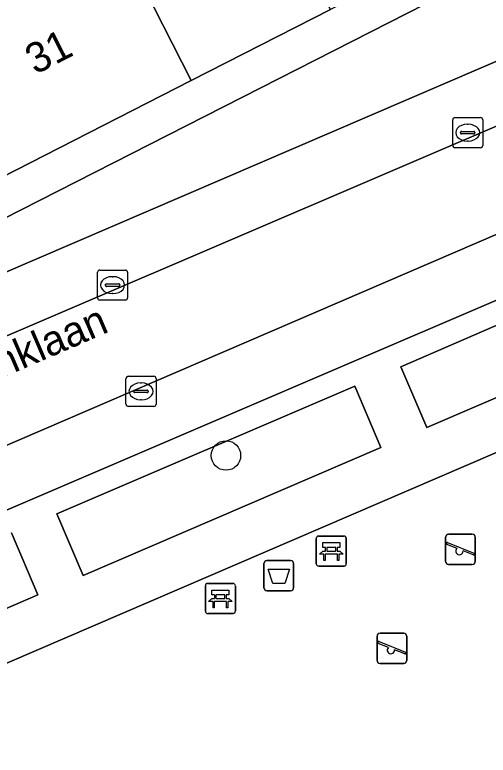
# Model space of a CAD drawing. Extents: x 162344 to 162869, y 381217 to 381818.
# Drawn here: x 162510.38 to 162526.14, y 381519.73 to 381544.36 of the extents above; entities that cross this region are included whole.
import ezdxf

# ---------------------------------------------------------------- set-up
doc = ezdxf.new("R2010")
doc.units = 0
for name, color, linetype in [('IMGEO_Afvalbak', 7, 'Continuous'), ('IMGEO_Bank', 7, 'Continuous'), ('IMGEO_Boom', 7, 'Continuous'), ('IMGEO_Erf', 7, 'Continuous'), ('IMGEO_Groenvoorziening', 7, 'Continuous'), ('IMGEO_Kolk', 7, 'Continuous'), ('IMGEO_Openbare_ruimte_label', 7, 'Continuous'), ('IMGEO_Pand', 7, 'Continuous'), ('IMGEO_Pand_nummerreeks', 7, 'Continuous'), ('IMGEO_Parkeervlak_open', 7, 'Continuous'), ('IMGEO_Rijbaan_lokaal_open', 7, 'Continuous'), ('IMGEO_Speelvoorziening', 7, 'Continuous'), ('IMGEO_Terreindeel_zand', 7, 'Continuous'), ('IMGEO_Voetpad_open', 7, 'Continuous')]:
    doc.layers.add(name, color=color, linetype=linetype)

msp = doc.modelspace()

# ---------------------------------------------------------------- linework, layer by layer
at = {"layer": 'IMGEO_Afvalbak'}
for p, q in [((162518.676, 381525.301), (162518.676, 381526.101)), ((162518.676, 381526.101), (162518.676, 381525.301)), ((162518.776, 381526.201), (162519.566, 381526.201)), ((162519.566, 381526.201), (162518.776, 381526.201)), ((162519.666, 381526.101), (162519.666, 381525.301)), ((162519.666, 381525.301), (162519.666, 381526.101)), ((162519.566, 381525.201), (162518.776, 381525.201)), ((162518.776, 381525.201), (162519.566, 381525.201))]:
    msp.add_line(p, q, dxfattribs=at)
msp.add_lwpolyline([(162518.819, 381525.915), (162519.523, 381525.915), (162519.374, 381525.445), (162518.968, 381525.445), (162518.819, 381525.915)], dxfattribs=at)
for centre, start, end in [((162518.776, 381526.101), 90, 180), ((162518.776, 381526.101), 90, 180), ((162519.566, 381526.101), 0, 90), ((162519.566, 381526.101), 360, 90), ((162518.776, 381525.301), 180, 270), ((162518.776, 381525.301), 180, 270), ((162519.566, 381525.301), 270, 0), ((162519.566, 381525.301), 270, 0)]:
    msp.add_arc(centre, 0.1, start, end, dxfattribs=at)
at = {"layer": 'IMGEO_Bank'}
for p, q in [((162520.42, 381526.095), (162520.42, 381526.936)), ((162520.42, 381526.936), (162520.42, 381526.095)), ((162520.495, 381527.02), (162521.336, 381527.02)), ((162521.336, 381527.02), (162520.495, 381527.02)), ((162521.42, 381526.945), (162521.42, 381526.104)), ((162521.42, 381526.104), (162521.42, 381526.945)), ((162520.729, 381526.526), (162520.729, 381526.632)), ((162520.773, 381526.632), (162520.773, 381526.526)), ((162521.061, 381526.638), (162520.779, 381526.638)), ((162521.067, 381526.526), (162521.067, 381526.632)), ((162521.111, 381526.632), (162521.111, 381526.526)), ((162521.117, 381526.418), (162520.724, 381526.418)), ((162520.779, 381526.52), (162521.061, 381526.52)), ((162521.345, 381526.02), (162520.504, 381526.02)), ((162520.504, 381526.02), (162521.345, 381526.02)), ((162516.728, 381524.518), (162516.728, 381525.359)), ((162516.728, 381525.359), (162516.728, 381524.518)), ((162516.803, 381525.443), (162517.644, 381525.443)), ((162517.644, 381525.443), (162516.803, 381525.443)), ((162517.728, 381525.368), (162517.728, 381524.527)), ((162517.728, 381524.527), (162517.728, 381525.368)), ((162517.037, 381524.949), (162517.037, 381525.055)), ((162517.081, 381525.055), (162517.081, 381524.949)), ((162517.369, 381525.061), (162517.087, 381525.061)), ((162517.375, 381524.949), (162517.375, 381525.055)), ((162517.419, 381525.055), (162517.419, 381524.949)), ((162517.425, 381524.841), (162517.032, 381524.841)), ((162517.087, 381524.943), (162517.369, 381524.943)), ((162517.653, 381524.443), (162516.812, 381524.443)), ((162516.812, 381524.443), (162517.653, 381524.443))]:
    msp.add_line(p, q, dxfattribs=at)
for points in [[(162520.723, 381526.638), (162520.637, 381526.638), (162520.637, 381526.799), (162521.2, 381526.799), (162521.2, 381526.638), (162521.117, 381526.638)], [(162520.667, 381526.418), (162520.525, 381526.418), (162520.637, 381526.52), (162520.723, 381526.52)], [(162520.717, 381526.411), (162520.717, 381526.204), (162520.674, 381526.204), (162520.674, 381526.411)], [(162521.117, 381526.52), (162521.2, 381526.52), (162521.312, 381526.418), (162521.173, 381526.418)], [(162521.167, 381526.411), (162521.167, 381526.204), (162521.123, 381526.204), (162521.123, 381526.411)], [(162517.031, 381525.061), (162516.945, 381525.061), (162516.945, 381525.222), (162517.508, 381525.222), (162517.508, 381525.061), (162517.425, 381525.061)], [(162516.975, 381524.841), (162516.833, 381524.841), (162516.945, 381524.943), (162517.031, 381524.943)], [(162517.025, 381524.834), (162517.025, 381524.627), (162516.982, 381524.627), (162516.982, 381524.834)], [(162517.425, 381524.943), (162517.508, 381524.943), (162517.62, 381524.841), (162517.481, 381524.841)], [(162517.475, 381524.834), (162517.475, 381524.627), (162517.431, 381524.627), (162517.431, 381524.834)]]:
    msp.add_lwpolyline(points, dxfattribs=at)
for centre, radius, start, end in [((162520.498, 381526.942), 0.0779, 92.4484, 184.2845), ((162520.498, 381526.942), 0.0779, 92.4484, 184.2845), ((162521.342, 381526.942), 0.0779, 2.4484, 94.2845), ((162521.342, 381526.942), 0.0779, 2.4484, 94.2845), ((162520.722, 381526.631), 0.00671, 2.8957, 87.1043), ((162520.779, 381526.631), 0.00671, 92.8957, 177.1043), ((162521.061, 381526.631), 0.00671, 2.8957, 87.1043), ((162521.118, 381526.631), 0.00671, 92.8957, 177.1043), ((162520.667, 381526.411), 0.00671, 2.8957, 87.1043), ((162520.724, 381526.411), 0.00671, 92.8957, 177.1043), ((162520.722, 381526.527), 0.00671, 272.8957, 357.1043), ((162520.779, 381526.527), 0.00671, 182.8957, 267.1043), ((162521.061, 381526.527), 0.00671, 272.8957, 357.1043), ((162521.118, 381526.527), 0.00671, 182.8957, 267.1043), ((162521.116, 381526.411), 0.00671, 2.8957, 87.1043), ((162521.173, 381526.411), 0.00671, 92.8957, 177.1043), ((162520.498, 381526.098), 0.0779, 182.4484, 274.2845), ((162520.498, 381526.098), 0.0779, 182.4484, 274.2845), ((162521.342, 381526.098), 0.0779, 272.4484, 4.2845), ((162521.342, 381526.098), 0.0779, 272.4484, 4.2845), ((162516.806, 381525.365), 0.0779, 92.4484, 184.2845), ((162516.806, 381525.365), 0.0779, 92.4484, 184.2845), ((162517.65, 381525.365), 0.0779, 2.4484, 94.2845), ((162517.65, 381525.365), 0.0779, 2.4484, 94.2845), ((162517.03, 381525.054), 0.00671, 2.8957, 87.1043), ((162517.087, 381525.054), 0.00671, 92.8957, 177.1043), ((162517.369, 381525.054), 0.00671, 2.8957, 87.1043), ((162517.426, 381525.054), 0.00671, 92.8957, 177.1043), ((162516.975, 381524.834), 0.00671, 2.8957, 87.1043), ((162517.032, 381524.834), 0.00671, 92.8957, 177.1043), ((162517.03, 381524.95), 0.00671, 272.8957, 357.1043), ((162517.087, 381524.95), 0.00671, 182.8957, 267.1043), ((162517.369, 381524.95), 0.00671, 272.8957, 357.1043), ((162517.426, 381524.95), 0.00671, 182.8957, 267.1043), ((162517.424, 381524.834), 0.00671, 2.8957, 87.1043), ((162517.481, 381524.834), 0.00671, 92.8957, 177.1043), ((162516.806, 381524.521), 0.0779, 182.4484, 274.2845), ((162516.806, 381524.521), 0.0779, 182.4484, 274.2845), ((162517.65, 381524.521), 0.0779, 272.4484, 4.2845), ((162517.65, 381524.521), 0.0779, 272.4484, 4.2845)]:
    msp.add_arc(centre, radius, start, end, dxfattribs=at)
at = {"layer": 'IMGEO_Boom'}
msp.add_circle((162517.413, 381529.699), 0.489, dxfattribs=at)
at = {"layer": 'IMGEO_Erf'}
msp.add_lwpolyline([(162532.638, 381549.091), (162532.073, 381550.22), (162525.378, 381546.813), (162520.892, 381544.53), (162516.259, 381542.172), (162509.427, 381538.695), (162509.986, 381537.559)], close=True, dxfattribs=at)
at = {"layer": 'IMGEO_Groenvoorziening'}
for points in [[(162538.381, 381539.216), (162523.23, 381532.652), (162524.096, 381530.629), (162537.402, 381536.341)], [(162499.674, 381520.107), (162511.154, 381525.065), (162510.27, 381527.123)]]:
    msp.add_lwpolyline(points, dxfattribs=at)
msp.add_lwpolyline([(162521.7, 381532.007), (162511.787, 381527.762), (162512.662, 381525.701), (162522.572, 381529.968)], close=True, dxfattribs=at)
at = {"layer": 'IMGEO_Kolk'}
for p, q in [((162524.96, 381540.012), (162524.96, 381540.864)), ((162525.035, 381540.938), (162525.887, 381540.938)), ((162525.961, 381540.864), (162525.961, 381540.012)), ((162525.448, 381540.718), (162525.473, 381540.718)), ((162525.219, 381540.432), (162525.219, 381540.444)), ((162525.657, 381540.395), (162525.259, 381540.395)), ((162525.262, 381540.481), (162525.66, 381540.481)), ((162525.703, 381540.444), (162525.703, 381540.432)), ((162525.471, 381540.158), (162525.446, 381540.158)), ((162525.887, 381539.938), (162525.035, 381539.938)), ((162513.138, 381534.941), (162513.138, 381535.793)), ((162513.213, 381535.867), (162514.065, 381535.867)), ((162513.626, 381535.647), (162513.651, 381535.647)), ((162514.139, 381535.793), (162514.139, 381534.941)), ((162513.44, 381535.41), (162513.838, 381535.41)), ((162513.397, 381535.361), (162513.397, 381535.373)), ((162513.835, 381535.324), (162513.437, 381535.324)), ((162513.881, 381535.373), (162513.881, 381535.361)), ((162513.649, 381535.087), (162513.624, 381535.087)), ((162514.065, 381534.867), (162513.213, 381534.867)), ((162514.085, 381531.406), (162514.085, 381532.258)), ((162514.16, 381532.332), (162515.012, 381532.332)), ((162515.086, 381532.258), (162515.086, 381531.406)), ((162514.573, 381532.112), (162514.598, 381532.112)), ((162514.344, 381531.826), (162514.344, 381531.838)), ((162514.782, 381531.789), (162514.384, 381531.789)), ((162514.387, 381531.875), (162514.785, 381531.875)), ((162514.828, 381531.838), (162514.828, 381531.826)), ((162514.596, 381531.552), (162514.571, 381531.552)), ((162515.012, 381531.332), (162514.16, 381531.332))]:
    msp.add_line(p, q, dxfattribs=at)
for points in [[(162524.96, 381540.012), (162524.96, 381540.864)], [(162525.035, 381540.938), (162525.887, 381540.938)], [(162525.961, 381540.864), (162525.961, 381540.012)], [(162525.887, 381539.938), (162525.035, 381539.938)], [(162513.138, 381534.941), (162513.138, 381535.793)], [(162513.213, 381535.867), (162514.065, 381535.867)], [(162514.139, 381535.793), (162514.139, 381534.941)], [(162514.065, 381534.867), (162513.213, 381534.867)], [(162514.085, 381531.406), (162514.085, 381532.258)], [(162514.16, 381532.332), (162515.012, 381532.332)], [(162515.086, 381532.258), (162515.086, 381531.406)], [(162515.012, 381531.332), (162514.16, 381531.332)]]:
    msp.add_lwpolyline(points, dxfattribs=at)
for centre, radius, start, end in [((162525.037, 381540.862), 0.0765, 91.552, 178.448), ((162525.037, 381540.862), 0.0765, 91.552, 178.448), ((162525.885, 381540.862), 0.0765, 1.552, 88.448), ((162525.885, 381540.862), 0.0765, 1.552, 88.448), ((162525.259, 381540.441), 0.0403, 85.8775, 175.7526), ((162525.256, 381540.431), 0.0366, 178.938, 274.7102), ((162525.66, 381540.438), 0.043, 264.8664, 352.4533), ((162525.664, 381540.443), 0.0386, 1.7309, 96.639), ((162525.037, 381540.014), 0.0765, 181.552, 268.448), ((162525.037, 381540.014), 0.0765, 181.552, 268.448), ((162525.885, 381540.014), 0.0765, 271.552, 358.448), ((162525.885, 381540.014), 0.0765, 271.552, 358.448), ((162513.215, 381535.791), 0.0765, 91.552, 178.448), ((162513.215, 381535.791), 0.0765, 91.552, 178.448), ((162514.063, 381535.791), 0.0765, 1.552, 88.448), ((162514.063, 381535.791), 0.0765, 1.552, 88.448), ((162513.437, 381535.37), 0.0403, 85.8775, 175.7526), ((162513.842, 381535.372), 0.0386, 1.7309, 96.639), ((162513.434, 381535.36), 0.0366, 178.938, 274.7102), ((162513.838, 381535.367), 0.043, 264.8664, 352.4533), ((162513.215, 381534.943), 0.0765, 181.552, 268.448), ((162513.215, 381534.943), 0.0765, 181.552, 268.448), ((162514.063, 381534.943), 0.0765, 271.552, 358.448), ((162514.063, 381534.943), 0.0765, 271.552, 358.448), ((162514.162, 381532.256), 0.0765, 91.552, 178.448), ((162514.162, 381532.256), 0.0765, 91.552, 178.448), ((162515.01, 381532.256), 0.0765, 1.552, 88.448), ((162515.01, 381532.256), 0.0765, 1.552, 88.448), ((162514.384, 381531.835), 0.0403, 85.8775, 175.7526), ((162514.381, 381531.825), 0.0366, 178.938, 274.7102), ((162514.785, 381531.832), 0.043, 264.8664, 352.4533), ((162514.789, 381531.837), 0.0386, 1.7309, 96.639), ((162514.162, 381531.408), 0.0765, 181.552, 268.448), ((162514.162, 381531.408), 0.0765, 181.552, 268.448), ((162515.01, 381531.408), 0.0765, 271.552, 358.448), ((162515.01, 381531.408), 0.0765, 271.552, 358.448)]:
    msp.add_arc(centre, radius, start, end, dxfattribs=at)
for centre, major_axis, ratio, start_param, end_param in [((162525.447, 381540.438), (-0.387, 0.002), 0.722429, 4.712389, 7.853982), ((162525.472, 381540.438), (-0.39, 0.002), 0.717154, 1.570796, 4.712389), ((162513.625, 381535.367), (-0.387, 0.002), 0.722429, 4.712389, 7.853982), ((162513.65, 381535.367), (-0.39, 0.002), 0.717154, 1.570796, 4.712389), ((162514.572, 381531.832), (-0.387, 0.002), 0.722429, 4.712389, 7.853982), ((162514.597, 381531.832), (-0.39, 0.002), 0.717154, 1.570796, 4.712389)]:
    msp.add_ellipse(centre, major_axis=major_axis, ratio=ratio, start_param=start_param, end_param=end_param, dxfattribs=at)
at = {"layer": 'IMGEO_Pand'}
for points in [[(162516.259, 381542.172), (162520.892, 381544.53), (162517.175, 381551.836), (162510.497, 381548.437), (162512.355, 381544.785), (162514.399, 381545.825)], [(162514.399, 381545.825), (162512.355, 381544.785), (162510.497, 381548.437), (162506.006, 381546.152), (162505.709, 381546.001), (162507.159, 381543.152), (162509.427, 381538.695), (162516.259, 381542.172)]]:
    msp.add_lwpolyline(points, close=True, dxfattribs=at)
at = {"layer": 'IMGEO_Parkeervlak_open'}
for points in [[(162529.63, 381544.187), (162503.672, 381533.049)], [(162501.836, 381530.146), (162533.181, 381543.553)], [(162534.166, 381540.393), (162495.993, 381523.971)], [(162499.714, 381523.434), (162531.993, 381537.251)]]:
    msp.add_lwpolyline(points, dxfattribs=at)
at = {"layer": 'IMGEO_Rijbaan_lokaal_open'}
msp.add_lwpolyline([(162471.49, 381571.265), (162464.059, 381585.948), (162463.431, 381587.185), (162460.5, 381585.739), (162491.571, 381524.186), (162491.709, 381523.952), (162492.43, 381522.496), (162492.451, 381522.505), (162495.827, 381523.884), (162495.993, 381523.971), (162534.166, 381540.393), (162534.297, 381540.457), (162534.943, 381540.72), (162533.689, 381543.768), (162533.404, 381543.643), (162533.181, 381543.553), (162501.836, 381530.146), (162501.509, 381530.036)], dxfattribs=at)
at = {"layer": 'IMGEO_Speelvoorziening'}
for p, q in [((162524.824, 381527.077), (162525.614, 381527.077)), ((162525.614, 381527.077), (162524.824, 381527.077)), ((162524.724, 381526.177), (162524.724, 381526.977)), ((162524.724, 381526.977), (162524.724, 381526.177)), ((162524.793, 381526.802), (162525.669, 381526.449)), ((162525.714, 381526.977), (162525.714, 381526.177)), ((162525.714, 381526.177), (162525.714, 381526.977)), ((162525.107, 381526.605), (162524.768, 381526.742)), ((162525.645, 381526.389), (162525.305, 381526.526)), ((162525.614, 381526.077), (162524.824, 381526.077)), ((162524.824, 381526.077), (162525.614, 381526.077)), ((162522.441, 381522.884), (162522.441, 381523.684)), ((162522.441, 381523.684), (162522.441, 381522.884)), ((162522.541, 381523.784), (162523.331, 381523.784)), ((162523.331, 381523.784), (162522.541, 381523.784)), ((162523.431, 381523.684), (162523.431, 381522.884)), ((162523.431, 381522.884), (162523.431, 381523.684)), ((162522.824, 381523.312), (162522.485, 381523.449)), ((162522.51, 381523.509), (162523.386, 381523.156)), ((162523.362, 381523.096), (162523.022, 381523.233)), ((162523.331, 381522.784), (162522.541, 381522.784)), ((162522.541, 381522.784), (162523.331, 381522.784))]:
    msp.add_line(p, q, dxfattribs=at)
for centre, radius, start, end in [((162524.824, 381526.977), 0.1, 90, 180), ((162524.824, 381526.977), 0.1, 90, 180), ((162525.614, 381526.977), 0.1, 0, 90), ((162525.614, 381526.977), 0.1, 360, 90), ((162524.781, 381526.772), 0.0327, 68.078, 248.078), ((162525.186, 381526.515), 0.12, 130.9928, 5.1632), ((162525.657, 381526.419), 0.0327, 248.078, 68.078), ((162524.824, 381526.177), 0.1, 180, 270), ((162524.824, 381526.177), 0.1, 180, 270), ((162525.614, 381526.177), 0.1, 270, 0), ((162525.614, 381526.177), 0.1, 270, 0), ((162522.541, 381523.684), 0.1, 90, 180), ((162522.541, 381523.684), 0.1, 90, 180), ((162523.331, 381523.684), 0.1, 0, 90), ((162523.331, 381523.684), 0.1, 360, 90), ((162522.498, 381523.479), 0.0327, 68.078, 248.078), ((162522.903, 381523.222), 0.12, 130.9928, 5.1632), ((162523.374, 381523.126), 0.0327, 248.078, 68.078), ((162522.541, 381522.884), 0.1, 180, 270), ((162522.541, 381522.884), 0.1, 180, 270), ((162523.331, 381522.884), 0.1, 270, 0), ((162523.331, 381522.884), 0.1, 270, 0)]:
    msp.add_arc(centre, radius, start, end, dxfattribs=at)
at = {"layer": 'IMGEO_Terreindeel_zand'}
msp.add_lwpolyline([(162531.132, 381531.827), (162508.217, 381521.986), (162509, 381520.416), (162514.4, 381509.584), (162536.683, 381520.695)], close=True, dxfattribs=at)
at = {"layer": 'IMGEO_Voetpad_open'}
for points in [[(162430.818, 381673.015), (162428.569, 381675.765), (162428.211, 381675.44), (162428.12, 381675.14), (162427.72, 381671.816), (162428.169, 381670.985), (162415.217, 381664.354), (162415.849, 381663.025), (162416.703, 381663.475), (162450.084, 381597.259), (162455.733, 381586.132), (162456.714, 381584.2), (162490.31, 381518.027), (162489.593, 381517.672), (162491.115, 381514.642), (162508.217, 381521.986), (162531.132, 381531.827), (162531.201, 381531.856), (162536.299, 381534.045), (162538.625, 381535.045), (162540.608, 381535.896), (162537.512, 381541.598)], [(162533.181, 381543.553), (162533.404, 381543.643), (162533.689, 381543.768), (162533.893, 381543.857), (162532.638, 381549.091), (162509.986, 381537.559), (162508.501, 381536.927), (162507.307, 381539.243), (162497.363, 381534.965), (162497.202, 381535.283), (162493.857, 381533.592), (162493.913, 381533.481), (162493.347, 381533.215), (162453.435, 381611.809), (162453.968, 381612.034), (162453.886, 381612.196), (162461.304, 381615.919), (162461.371, 381615.787), (162465.983, 381618.274)], [(162503.672, 381533.049), (162529.63, 381544.187)], [(162537.402, 381536.341), (162524.096, 381530.629), (162523.23, 381532.652), (162538.381, 381539.216)], [(162531.993, 381537.251), (162499.714, 381523.434)], [(162510.27, 381527.123), (162511.154, 381525.065), (162499.674, 381520.107)]]:
    msp.add_lwpolyline(points, dxfattribs=at)
msp.add_lwpolyline([(162521.7, 381532.007), (162522.572, 381529.968), (162512.662, 381525.701), (162511.787, 381527.762)], close=True, dxfattribs=at)

# ---------------------------------------------------------------- texts
at = {"layer": 'IMGEO_Openbare_ruimte_label'}
msp.add_text('Heggeranklaan', height=1, rotation=23.334, dxfattribs=at).set_placement((162505.233, 381530.234))
at = {"layer": 'IMGEO_Pand_nummerreeks'}
msp.add_text('31', height=1, rotation=26.9749, dxfattribs=at).set_placement((162511.064, 381542.355))

doc.saveas('drawing.dxf')
